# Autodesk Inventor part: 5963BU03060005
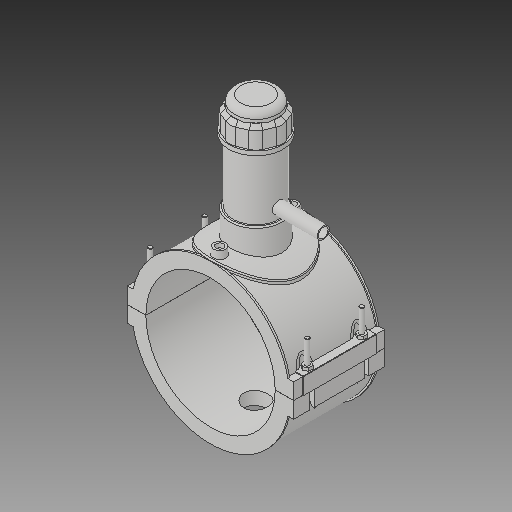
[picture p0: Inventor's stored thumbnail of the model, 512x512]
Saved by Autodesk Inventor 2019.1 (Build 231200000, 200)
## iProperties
Created: 2017-07
Part Number: 5963BU03060005
Material: Generic
Description: PLASSON TAPPING SADDLE 6''IPS x 1 1/2''CTS
Document SubType Name: Modeling
Designer: KIM
Mass: 1712.7 g
Surface Area: 2671.49 cm^2
Volume: 1712.7 cm^3
Density: 1 g/cm^3
Appearance: Default
Author: KIM
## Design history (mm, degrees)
derived "5963B.ipt"
feature "Solid1::5963B.ipt"
feature "Solid2::5963B.ipt"
feature "Solid4::5963B.ipt"
feature "Solid5::5963B.ipt"
tag "TaggingFeature1"
body "Solid1"
body "Solid2"
other parameters: "d0" = 168, "d2" = 215.9, "d3" = 42, "d4" = 118.11, "d5" = 0, "d6" = 0.1, "d8" = 0, "d19" = 6, "d20" = 6, "d21" = 70.866, "d23" = 0, "d24" = 35.433, "d26" = 0, "d29" = 3, "d30" = 56, "d31" = 6, "d32" = 0, "d33" = 0, "d34" = 0.6, "d40" = 104.832, "d41" = 117.6, "d43" = 0, "d45" = 0, "d47" = 171.666, "d70" = 15, "d72" = 0, "d73" = 6, "d75" = 5, "d76" = 0, "d77" = 8.4, "d78" = 114, "d79" = 15, "d80" = 47.244, "d82" = 5 deg, "d84" = 4, "d85" = 14, "d86" = 0, "d87" = 3, "d88" = 0, "d89" = 1, "d90" = 1, "d91" = 94.488, "d92" = 0, "d93" = 0.5, "d94" = 88.42105, "d96" = 205.632, "d97" = 2.3622, "d98" = 0, "d102" = 1.68, "d120" = 140 deg, "d121" = 24.228, "d122" = 20 deg, "d123" = 403.2, "d124" = 120.96, "d126" = 0, "d143" = 173.04, "d145" = 25.84615, "d149" = 2.52, "d150" = 28.43077, "d153" = 118.11, "d154" = 0, "d156" = 100.8, "d157" = 160 deg, "d159" = 6.72, "d161" = 2.52, "d162" = 70.866, "d163" = 0, "d164" = 84, "d167" = 16.8, "d168" = 98.34146, "d170" = 3.2805, "d172" = 0, "d173" = 1, "d175" = 84, "d176" = 20 deg, "d177" = 11.76, "d178" = 33.6, "d180" = 0, "d183" = 13.44, "d184" = 9.408, "d185" = 38.38575, "d186" = 38.38575, "d187" = 100.8, "d188" = 10.08, "d189" = 11.76, "d190" = 0, "d191" = 151.2, "d193" = 6.1236, "d194" = 4.13385, "d195" = 90 deg, "d197" = 0, "d199" = 0, "d200" = 16.8, "d202" = 0, "d203" = 177.038, "d204" = 67.032, "d205" = 49.392, "d206" = 59.976, "d207" = 132.7785, "d208" = 138.08964, "d209" = 164.64534, "d210" = 60.6816, "d211" = 70.56, "d212" = 56.448, "d213" = 51.4116, "d216" = 0, "d217" = 16.8, "d218" = 8.4, "d219" = 1.68, "d222" = 168, "d224" = 0, "d230" = 5.04, "d233" = 6, "d236" = 107.95, "d237" = 35.433, "d238" = 6.02433, "d240" = 35.433, "d241" = 35.433, "d242" = 35.433, "d243" = 6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
